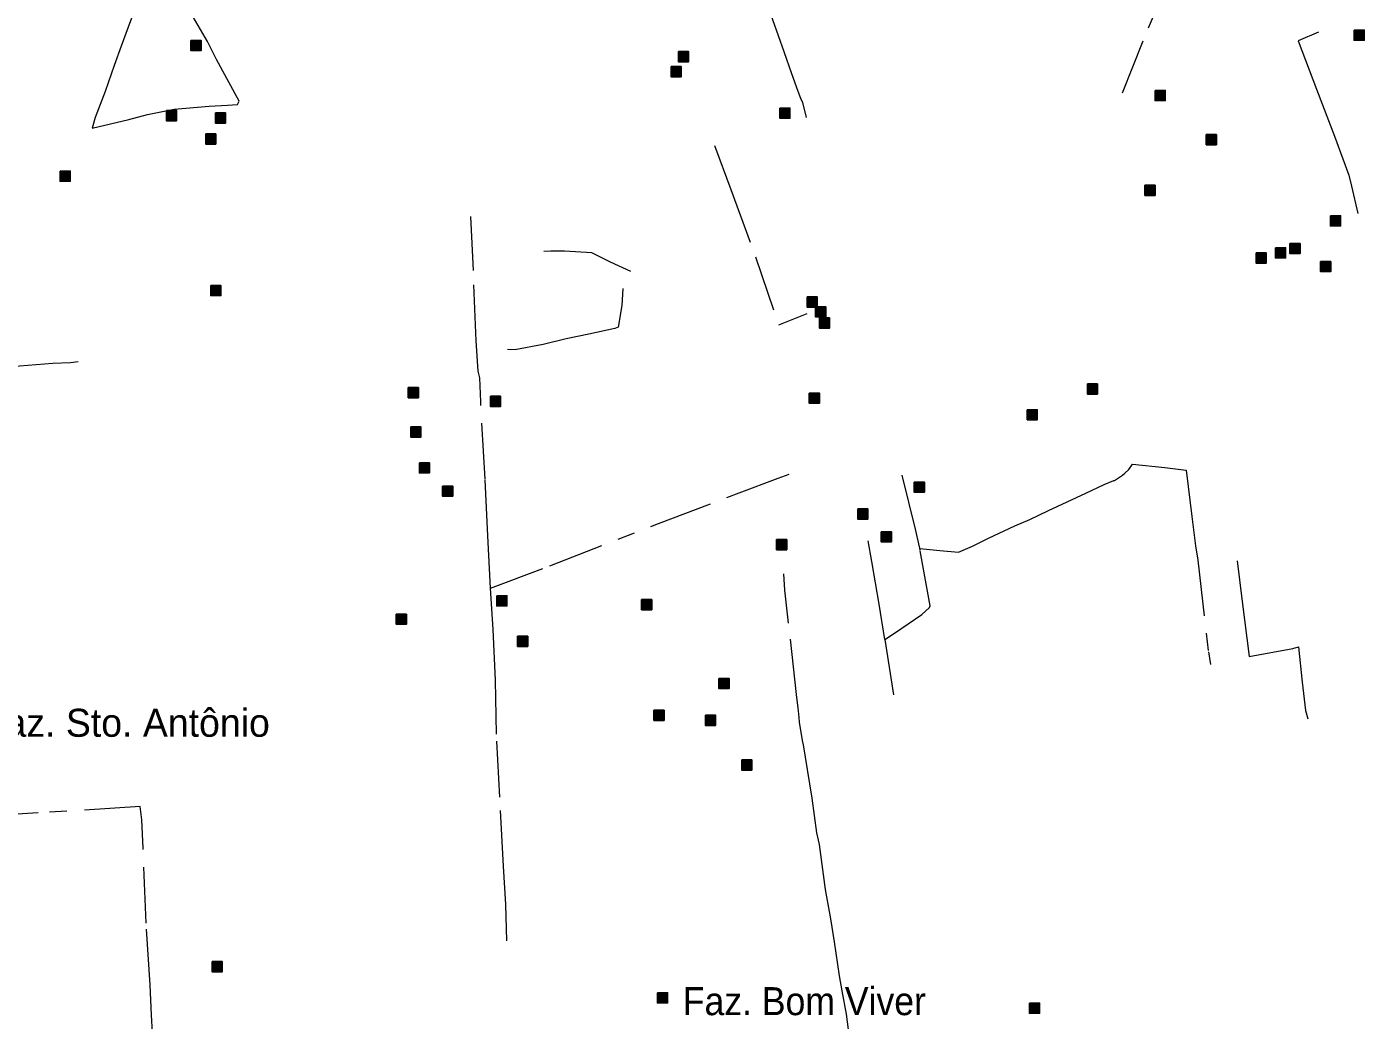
# Model space of a CAD drawing. Extents: x 393.5 to 446.9, y 8064.8 to 8120.4.
# Drawn here: x 425 to 432.64, y 8070.5 to 8076.18 of the extents above; entities that cross this region are included whole.
import ezdxf

# ---------------------------------------------------------------- set-up
doc = ezdxf.new("R2010")
doc.units = 0
doc.header["$LTSCALE"] = 0.064
doc.linetypes.add('DOT_DASHED', pattern=[7.7, 5, -1.2, 0.3, -1.2])
doc.layers.add('2', color=7, linetype='Continuous', lineweight=25)
doc.layers.add('22', color=7, linetype='DOT_DASHED', lineweight=13)
doc.layers.add('61', color=7, linetype='Continuous')

msp = doc.modelspace()

# ---------------------------------------------------------------- hatches: boundary and pattern name
at = {"layer": '2'}
for points in [[(432.5815, 8076.1572), (432.6395, 8076.1572), (432.6395, 8076.0992), (432.5815, 8076.0992)], [(425.9338, 8076.0988), (425.9918, 8076.0988), (425.9918, 8076.0408), (425.9338, 8076.0408)], [(428.7202, 8076.0349), (428.7782, 8076.0349), (428.7782, 8075.9769), (428.7202, 8075.9769)], [(428.6781, 8075.9485), (428.7361, 8075.9485), (428.7361, 8075.8905), (428.6781, 8075.8905)], [(431.4445, 8075.8129), (431.5025, 8075.8129), (431.5025, 8075.7549), (431.4445, 8075.7549)], [(425.794, 8075.6978), (425.852, 8075.6978), (425.852, 8075.6398), (425.794, 8075.6398)], [(426.0741, 8075.684), (426.1321, 8075.684), (426.1321, 8075.626), (426.0741, 8075.626)], [(429.2996, 8075.7114), (429.3576, 8075.7114), (429.3576, 8075.6534), (429.2996, 8075.6534)], [(426.0182, 8075.5643), (426.0762, 8075.5643), (426.0762, 8075.5063), (426.0182, 8075.5063)], [(431.7366, 8075.5601), (431.7946, 8075.5601), (431.7946, 8075.5021), (431.7366, 8075.5021)], [(425.1858, 8075.3516), (425.2438, 8075.3516), (425.2438, 8075.2936), (425.1858, 8075.2936)], [(431.3859, 8075.2711), (431.4439, 8075.2711), (431.4439, 8075.2131), (431.3859, 8075.2131)], [(432.4459, 8075.0961), (432.5039, 8075.0961), (432.5039, 8075.0381), (432.4459, 8075.0381)], [(432.1316, 8074.9137), (432.1896, 8074.9137), (432.1896, 8074.8557), (432.1316, 8074.8557)], [(432.2144, 8074.9381), (432.2724, 8074.9381), (432.2724, 8074.8801), (432.2144, 8074.8801)], [(432.0212, 8074.8841), (432.0792, 8074.8841), (432.0792, 8074.8261), (432.0212, 8074.8261)], [(432.3899, 8074.8351), (432.4479, 8074.8351), (432.4479, 8074.7771), (432.3899, 8074.7771)], [(426.0472, 8074.6979), (426.1052, 8074.6979), (426.1052, 8074.6399), (426.0472, 8074.6399)], [(429.4551, 8074.6329), (429.5131, 8074.6329), (429.5131, 8074.5749), (429.4551, 8074.5749)], [(429.5043, 8074.5764), (429.5623, 8074.5764), (429.5623, 8074.5184), (429.5043, 8074.5184)], [(429.5255, 8074.5129), (429.5835, 8074.5129), (429.5835, 8074.4549), (429.5255, 8074.4549)], [(431.057, 8074.1359), (431.115, 8074.1359), (431.115, 8074.0779), (431.057, 8074.0779)], [(427.1757, 8074.1148), (427.2337, 8074.1148), (427.2337, 8074.0568), (427.1757, 8074.0568)], [(427.6454, 8074.0654), (427.7034, 8074.0654), (427.7034, 8074.0074), (427.6454, 8074.0074)], [(429.4674, 8074.0832), (429.5254, 8074.0832), (429.5254, 8074.0252), (429.4674, 8074.0252)], [(430.7131, 8073.9884), (430.7711, 8073.9884), (430.7711, 8073.9304), (430.7131, 8073.9304)], [(427.19, 8073.8894), (427.248, 8073.8894), (427.248, 8073.8314), (427.19, 8073.8314)], [(427.2393, 8073.6851), (427.2973, 8073.6851), (427.2973, 8073.6271), (427.2393, 8073.6271)], [(427.3726, 8073.5514), (427.4306, 8073.5514), (427.4306, 8073.4934), (427.3726, 8073.4934)], [(430.0674, 8073.5742), (430.1254, 8073.5742), (430.1254, 8073.5162), (430.0674, 8073.5162)], [(429.7452, 8073.4209), (429.8032, 8073.4209), (429.8032, 8073.3629), (429.7452, 8073.3629)], [(429.8794, 8073.2908), (429.9374, 8073.2908), (429.9374, 8073.2328), (429.8794, 8073.2328)], [(429.2811, 8073.2457), (429.3391, 8073.2457), (429.3391, 8073.1877), (429.2811, 8073.1877)], [(427.6816, 8072.9252), (427.7396, 8072.9252), (427.7396, 8072.8672), (427.6816, 8072.8672)], [(428.5093, 8072.903), (428.5673, 8072.903), (428.5673, 8072.845), (428.5093, 8072.845)], [(427.1071, 8072.8198), (427.1651, 8072.8198), (427.1651, 8072.7618), (427.1071, 8072.7618)], [(427.801, 8072.6933), (427.859, 8072.6933), (427.859, 8072.6353), (427.801, 8072.6353)], [(428.9517, 8072.4524), (429.0097, 8072.4524), (429.0097, 8072.3944), (428.9517, 8072.3944)], [(428.5798, 8072.2709), (428.6378, 8072.2709), (428.6378, 8072.2129), (428.5798, 8072.2129)], [(428.8745, 8072.2421), (428.9325, 8072.2421), (428.9325, 8072.1841), (428.8745, 8072.1841)], [(429.0823, 8071.9872), (429.1403, 8071.9872), (429.1403, 8071.9292), (429.0823, 8071.9292)], [(426.0546, 8070.8342), (426.1126, 8070.8342), (426.1126, 8070.7762), (426.0546, 8070.7762)], [(428.6002, 8070.6564), (428.6582, 8070.6564), (428.6582, 8070.5984), (428.6002, 8070.5984)], [(430.7257, 8070.5976), (430.7837, 8070.5976), (430.7837, 8070.5396), (430.7257, 8070.5396)]]:
    msp.add_hatch(color=256, dxfattribs=at).paths.add_polyline_path(points)

# ---------------------------------------------------------------- linework, layer by layer
for points in [[(432.5815, 8076.1572), (432.6395, 8076.1572), (432.6395, 8076.0992), (432.5815, 8076.0992)], [(425.9338, 8076.0988), (425.9918, 8076.0988), (425.9918, 8076.0408), (425.9338, 8076.0408)], [(428.7202, 8076.0349), (428.7782, 8076.0349), (428.7782, 8075.9769), (428.7202, 8075.9769)], [(428.6781, 8075.9485), (428.7361, 8075.9485), (428.7361, 8075.8905), (428.6781, 8075.8905)], [(431.4445, 8075.8129), (431.5025, 8075.8129), (431.5025, 8075.7549), (431.4445, 8075.7549)], [(425.794, 8075.6978), (425.852, 8075.6978), (425.852, 8075.6398), (425.794, 8075.6398)], [(426.0741, 8075.684), (426.1321, 8075.684), (426.1321, 8075.626), (426.0741, 8075.626)], [(429.2996, 8075.7114), (429.3576, 8075.7114), (429.3576, 8075.6534), (429.2996, 8075.6534)], [(426.0182, 8075.5643), (426.0762, 8075.5643), (426.0762, 8075.5063), (426.0182, 8075.5063)], [(431.7366, 8075.5601), (431.7946, 8075.5601), (431.7946, 8075.5021), (431.7366, 8075.5021)], [(425.1858, 8075.3516), (425.2438, 8075.3516), (425.2438, 8075.2936), (425.1858, 8075.2936)], [(431.3859, 8075.2711), (431.4439, 8075.2711), (431.4439, 8075.2131), (431.3859, 8075.2131)], [(432.4459, 8075.0961), (432.5039, 8075.0961), (432.5039, 8075.0381), (432.4459, 8075.0381)], [(432.1316, 8074.9137), (432.1896, 8074.9137), (432.1896, 8074.8557), (432.1316, 8074.8557)], [(432.2144, 8074.9381), (432.2724, 8074.9381), (432.2724, 8074.8801), (432.2144, 8074.8801)], [(432.0212, 8074.8841), (432.0792, 8074.8841), (432.0792, 8074.8261), (432.0212, 8074.8261)], [(432.3899, 8074.8351), (432.4479, 8074.8351), (432.4479, 8074.7771), (432.3899, 8074.7771)], [(426.0472, 8074.6979), (426.1052, 8074.6979), (426.1052, 8074.6399), (426.0472, 8074.6399)], [(429.4551, 8074.6329), (429.5131, 8074.6329), (429.5131, 8074.5749), (429.4551, 8074.5749)], [(429.5043, 8074.5764), (429.5623, 8074.5764), (429.5623, 8074.5184), (429.5043, 8074.5184)], [(429.5255, 8074.5129), (429.5835, 8074.5129), (429.5835, 8074.4549), (429.5255, 8074.4549)], [(431.057, 8074.1359), (431.115, 8074.1359), (431.115, 8074.0779), (431.057, 8074.0779)], [(427.1757, 8074.1148), (427.2337, 8074.1148), (427.2337, 8074.0568), (427.1757, 8074.0568)], [(427.6454, 8074.0654), (427.7034, 8074.0654), (427.7034, 8074.0074), (427.6454, 8074.0074)], [(429.4674, 8074.0832), (429.5254, 8074.0832), (429.5254, 8074.0252), (429.4674, 8074.0252)], [(430.7131, 8073.9884), (430.7711, 8073.9884), (430.7711, 8073.9304), (430.7131, 8073.9304)], [(427.19, 8073.8894), (427.248, 8073.8894), (427.248, 8073.8314), (427.19, 8073.8314)], [(427.2393, 8073.6851), (427.2973, 8073.6851), (427.2973, 8073.6271), (427.2393, 8073.6271)], [(427.3726, 8073.5514), (427.4306, 8073.5514), (427.4306, 8073.4934), (427.3726, 8073.4934)], [(430.0674, 8073.5742), (430.1254, 8073.5742), (430.1254, 8073.5162), (430.0674, 8073.5162)], [(429.7452, 8073.4209), (429.8032, 8073.4209), (429.8032, 8073.3629), (429.7452, 8073.3629)], [(429.8794, 8073.2908), (429.9374, 8073.2908), (429.9374, 8073.2328), (429.8794, 8073.2328)], [(429.2811, 8073.2457), (429.3391, 8073.2457), (429.3391, 8073.1877), (429.2811, 8073.1877)], [(427.6816, 8072.9252), (427.7396, 8072.9252), (427.7396, 8072.8672), (427.6816, 8072.8672)], [(428.5093, 8072.903), (428.5673, 8072.903), (428.5673, 8072.845), (428.5093, 8072.845)], [(427.1071, 8072.8198), (427.1651, 8072.8198), (427.1651, 8072.7618), (427.1071, 8072.7618)], [(427.801, 8072.6933), (427.859, 8072.6933), (427.859, 8072.6353), (427.801, 8072.6353)], [(428.9517, 8072.4524), (429.0097, 8072.4524), (429.0097, 8072.3944), (428.9517, 8072.3944)], [(428.5798, 8072.2709), (428.6378, 8072.2709), (428.6378, 8072.2129), (428.5798, 8072.2129)], [(428.8745, 8072.2421), (428.9325, 8072.2421), (428.9325, 8072.1841), (428.8745, 8072.1841)], [(429.0823, 8071.9872), (429.1403, 8071.9872), (429.1403, 8071.9292), (429.0823, 8071.9292)], [(426.0546, 8070.8342), (426.1126, 8070.8342), (426.1126, 8070.7762), (426.0546, 8070.7762)], [(428.6002, 8070.6564), (428.6582, 8070.6564), (428.6582, 8070.5984), (428.6002, 8070.5984)], [(430.7257, 8070.5976), (430.7837, 8070.5976), (430.7837, 8070.5396), (430.7257, 8070.5396)]]:
    msp.add_lwpolyline(points, close=True, dxfattribs=at)
at = {"layer": '22'}
msp.add_line((429.8998, 8072.6758), (429.9536, 8072.3265), dxfattribs=at)
for points in [[(429.0439, 8076.7867), (429.0575, 8076.7579), (429.086, 8076.6918), (429.1206, 8076.5922), (429.1866, 8076.4179), (429.2258, 8076.3088), (429.3233, 8076.0354), (429.3663, 8075.9096), (429.4022, 8075.8088), (429.4183, 8075.768), (429.4282, 8075.7428), (429.4492, 8075.6575)], [(425.7307, 8076.6047), (425.6957, 8076.5025), (425.6275, 8076.3101), (425.5877, 8076.2106), (425.535, 8076.0658), (425.4952, 8075.9558), (425.4446, 8075.8058), (425.3865, 8075.6572), (425.3727, 8075.6112), (425.3696, 8075.5963), (425.5794, 8075.6468), (425.685, 8075.6751), (425.8374, 8075.7055), (426.038, 8075.7219), (426.1436, 8075.7278), (426.1994, 8075.7316), (426.2102, 8075.7509), (426.0793, 8075.9893), (426.0288, 8076.0918), (425.9361, 8076.2515), (425.9217, 8076.282)], [(431.2585, 8075.7987), (431.4061, 8076.1701), (431.5599, 8076.5309), (431.5976, 8076.6253)], [(432.3775, 8076.1463), (432.2626, 8076.0961), (432.3659, 8075.8208), (432.4693, 8075.5506), (432.5517, 8075.329), (432.5666, 8075.2655), (432.6022, 8075.1098)], [(428.927, 8075.498), (429.0197, 8075.2458), (429.1603, 8074.8617), (429.293, 8074.4732), (429.4555, 8074.5373)], [(427.5752, 8074.208), (427.5633, 8074.3813), (427.5481, 8074.7829), (427.533, 8075.0917)], [(428.4472, 8074.7787), (428.3327, 8074.8314), (428.2251, 8074.8843), (428.0688, 8074.8943), (427.9907, 8074.8943), (427.9512, 8074.893)], [(428.4032, 8074.6815), (428.3973, 8074.5828), (428.3752, 8074.4598), (428.3575, 8074.4527), (428.2087, 8074.4198), (428.0775, 8074.394), (427.9463, 8074.3611), (427.7857, 8074.3297), (427.7436, 8074.3327)], [(422.5115, 8073.8435), (422.5115, 8073.847), (422.5109, 8073.8561), (422.5013, 8073.9993), (422.4847, 8074.1279), (422.4869, 8074.1793), (422.5631, 8074.1814), (422.8391, 8074.1814), (423.0649, 8074.1787), (423.432, 8074.175), (423.7472, 8074.1734), (423.9879, 8074.1745), (424.0682, 8074.1745), (424.2868, 8074.1873), (424.4933, 8074.198), (424.6048, 8074.2077), (424.6941, 8074.215), (424.9062, 8074.2355), (425.1447, 8074.2548), (425.2452, 8074.258), (425.2904, 8074.2633)], [(427.6455, 8072.969), (427.631, 8073.2675), (427.6152, 8073.592), (427.5902, 8074.0329), (427.5842, 8074.17), (427.5752, 8074.208)], [(431.2572, 8073.6132), (431.2716, 8073.6248), (431.2932, 8073.6458), (431.3149, 8073.6765), (431.5, 8073.6587), (431.6217, 8073.6426), (431.6542, 8073.378), (431.6759, 8073.2098), (431.6884, 8073.1281), (431.7493, 8072.6037), (431.7599, 8072.5327)], [(427.6455, 8072.969), (427.9843, 8073.0958), (428.6052, 8073.3371), (429.0666, 8073.5133), (429.2903, 8073.597), (429.3524, 8073.6205)], [(429.9961, 8073.6132), (430.0722, 8073.3058), (430.0982, 8073.1967), (430.0988, 8073.1942)], [(431.2093, 8073.583), (431.2113, 8073.5839), (431.2572, 8073.6132)], [(430.0988, 8073.1942), (430.2131, 8073.1837), (430.3214, 8073.174), (430.4015, 8073.208), (430.4915, 8073.2533), (430.6426, 8073.3244), (430.7276, 8073.3616), (430.8343, 8073.4117), (431.0477, 8073.5104), (431.1527, 8073.5606), (431.2093, 8073.583)], [(429.8998, 8072.6758), (429.8673, 8072.8765), (429.8248, 8073.1217), (429.8036, 8073.2393)], [(429.8998, 8072.6758), (429.9549, 8072.7106), (430.1106, 8072.8181), (430.1555, 8072.8573), (430.1579, 8072.8667), (430.1006, 8073.185), (430.0988, 8073.1942)], [(431.9139, 8073.1239), (431.9415, 8072.8916), (431.9814, 8072.5782), (432.2318, 8072.6235), (432.2634, 8072.6341), (432.2847, 8072.4316), (432.3038, 8072.2698), (432.3174, 8072.2214)], [(429.4051, 8072.2824), (429.3952, 8072.3599), (429.3497, 8072.7681), (429.3277, 8072.9565), (429.3225, 8073.051)], [(427.7393, 8070.9532), (427.7335, 8071.1609), (427.7212, 8071.3791), (427.6997, 8071.7748), (427.6803, 8072.1349), (427.6751, 8072.4433), (427.6619, 8072.7319), (427.6455, 8072.969)], [(429.7755, 8069.9239), (429.7112, 8070.3075), (429.6798, 8070.5338), (429.6553, 8070.6679), (429.6408, 8070.7538), (429.6116, 8070.947), (429.5918, 8071.0786), (429.5603, 8071.2467), (429.527, 8071.5031), (429.5113, 8071.571), (429.4842, 8071.7687), (429.4316, 8072.0871), (429.4123, 8072.2022), (429.4107, 8072.2302), (429.4066, 8072.2667), (429.4051, 8072.2824)], [(425.6538, 8071.6448), (425.6447, 8071.7206), (425.0617, 8071.6837), (424.9111, 8071.6759), (424.5378, 8071.6506), (424.3331, 8071.637), (424.1344, 8071.6234)], [(425.0414, 8068.6771), (425.0626, 8068.701), (425.0826, 8068.7458), (425.1208, 8068.8335), (425.1669, 8068.9367), (425.2091, 8069.0283), (425.2452, 8069.1101), (425.3426, 8069.335), (425.3928, 8069.446), (425.4409, 8069.5551), (425.5524, 8069.8034), (425.6046, 8069.9066), (425.6959, 8070.1257), (425.728, 8070.1939), (425.722, 8070.2971), (425.7089, 8070.5279), (425.7009, 8070.7012), (425.6778, 8071.0548), (425.6607, 8071.482), (425.6538, 8071.6448)]]:
    msp.add_lwpolyline(points, dxfattribs=at)

# ---------------------------------------------------------------- texts
at = {"layer": '61'}
msp.add_text('Faz. Sto. Antônio', height=0.16, dxfattribs=at).set_placement((424.7437, 8072.1192))
at = {"layer": '61', "width": 0.95}
msp.add_text('Faz. Bom Viver', height=0.16, dxfattribs=at).set_placement((428.745, 8070.5284))

doc.saveas('drawing.dxf')
